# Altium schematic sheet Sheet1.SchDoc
size 431 x 279 mm; SheetNumber: 1; SheetTotal: 1; ENG_APP_DATE: --/--/--; DSN_APP_DATE: --/--/--; CHK_APP_DATE: --/--/--
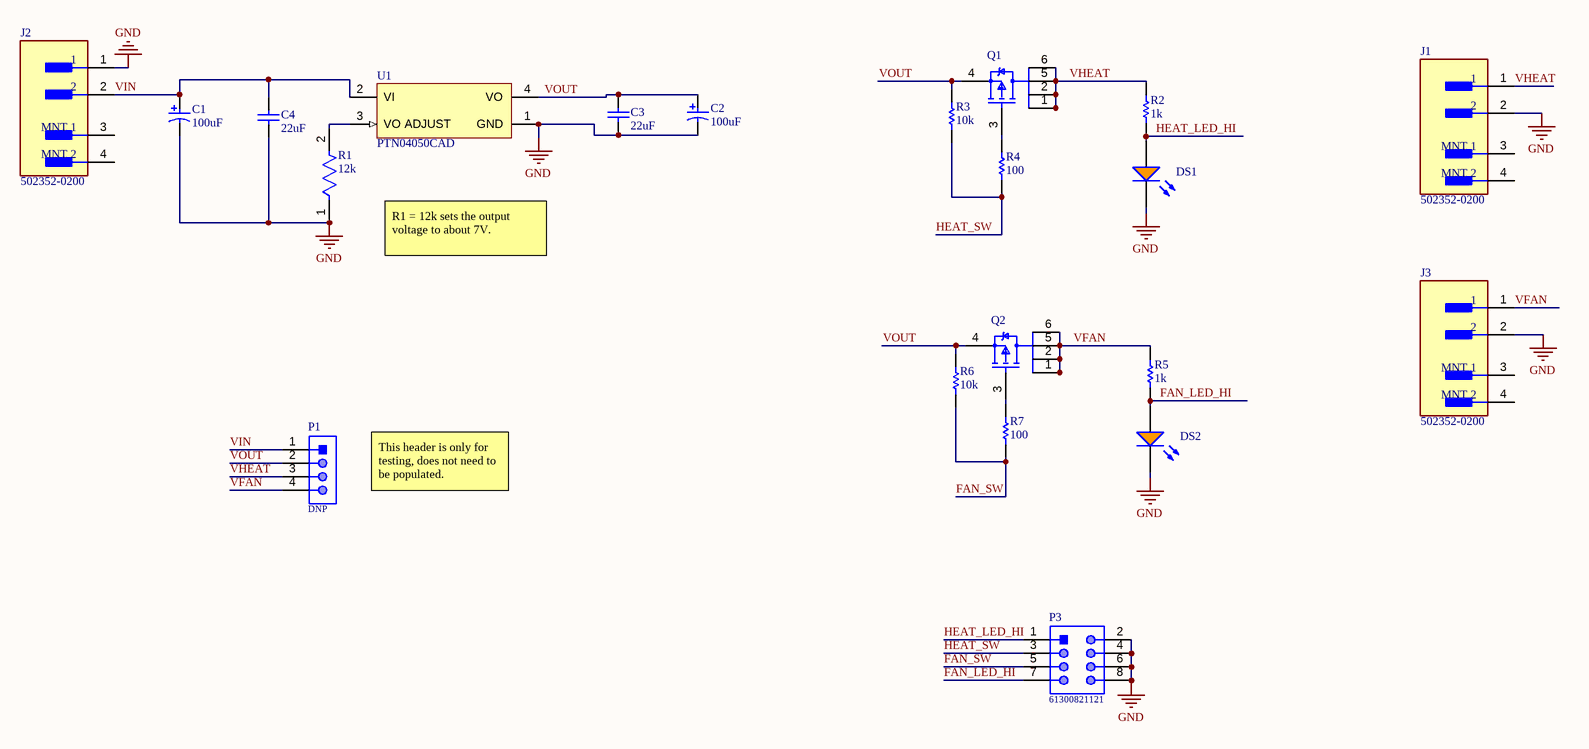
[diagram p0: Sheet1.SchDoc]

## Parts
C1  100uF  [PNSC-FK-V-D8_V]
C2  100uF  [PNSC-FK-V-D8_V]
C3  22uF  [MURA-1210_H_2.7_L]
C4  22uF  [MURA-1210_H_2.7_L]
DS1  HSMD-C170  [AVAG-HSMX-C170_V]  (value not drawn)
DS2  HSMD-C170  [AVAG-HSMX-C170_V]  (value not drawn)
J1  502352-0200  [FP-502352-0200-MFG]
J2  502352-0200  [FP-502352-0200-MFG]
J3  502352-0200  [FP-502352-0200-MFG]
P1  DNP  [61300411121]
P3  61300821121  [61300821121]
Q1  SI3493DDV-T1-GE3  [FP-C-06593-MFG]  (value not drawn)
Q2  SI3493DDV-T1-GE3  [FP-C-06593-MFG]  (value not drawn)
R1  12k  [FP-CRCW0805-e3-IPC_A]
R2  1k  [RESC2013X55X40LL15T20]
R3  10k  [RESC2013X60X35NL10T20]
R4  100  [RESC2013X50X30LL20T20]
R5  1k  [RESC2013X55X40LL15T20]
R6  10k  [RESC2013X60X35NL10T20]
R7  100  [RESC2013X50X30LL20T20]
U1  PTN04050CAD  [EUU0004A]

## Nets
GND: C1.2 C2.2 C3.1 C4.2 DS1.2(K) DS2.2(K) J1.2 J2.1 J3.2 P3.2 P3.4 P3.6 P3.8 R1.1 U1.1(GND)
FAN_LED_HI: DS2.1(A) P3.7 R5.1
FAN_SW: P3.5 R6.2 R7.1
HEAT_LED_HI: DS1.1(A) P3.1 R2.1
HEAT_SW: P3.3 R3.2 R4.1
VFAN: J3.1 P1.4 Q2.1(D) Q2.2(D) Q2.5(D) Q2.6(D) R5.2
VHEAT: J1.1 P1.3 Q1.1(D) Q1.2(D) Q1.5(D) Q1.6(D) R2.2
VIN: C1.1 C4.1 J2.2 P1.1 U1.2(VI)
VOUT: C2.1 C3.2 P1.2 Q1.4(S) Q2.4(S) R3.1 R6.1 U1.4(VO)
NetQ1_3: Q1.3(G) R4.2
NetQ2_3: Q2.3(G) R7.2
NetR1_2: R1.2 U1.3(VO_ADJUST)

Not connected (* = marked no-connect by the designer): J1 3(MNT_1) 4(MNT_2); J2 3(MNT_1) 4(MNT_2); J3 3(MNT_1) 4(MNT_2)

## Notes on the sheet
- R1 = 12k sets the output voltage to about 7V.
- This header is only for testing, does not need to be populated.

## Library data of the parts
C1 C2 = CMP-2000-06206-1: Aluminum Electrolytic Capacitor, 100 uF, +/- 20%, 25 V, 2-Pin SMD (Size Code D8), -55 to 105 degC, RoHS, Tape and Reel; Manufacturer: Panasonic; Type: Can; Lifetime@Temperature: 2000Hrs@105°C; Capacitance: 100µF; Rated Voltage: 25V; Ripple Current: 280mA; Impedance: 0.34O
C3 C4 = CMP-2000-06361-1: Chip Monolithic Ceramic Capacitor, 22 uF, +/- 10%, -55 to 85 degC, 2-Pin SMD (1210), RoHS, Tape and Reel; Manufacturer: Murata; Product Training Modules: High-CapMultilayerCeramicCapacitors; Other Names: 490-1882-2; Online Catalog: GRMSeries; Voltage Rating DC: 16V; Temperature Coefficient: X5R; Capacitance: 22µF; Catalog Drawings: GRMSeries_1210_2.5; Featured Product: GA3SafetyRecognizedCapsandHi-CapMLCC
DS1 DS2 = CMP-2000-06421-1: LED Uni-Color Orange, 52 mW, 20 mA, -40 to 85 degC, 2-Pin SMD, RoHS, Tape and Reel; Manufacturer: Avago; Forward Current If Max: 20mA; External Length / Height: 2mm; Luminous Intensity: 8mcd; Lens Shape: Rectangular; Bulb Size: 1.25mmx1.4mm; External Width: 1.25mm; Wavelength Typ: 605nm; Dominant Wavelength: 604nm; PIV Max: 5V; Opto Mounting Orientation: Top; Viewing Angle: 170°; LED Type: Standard; Forward Voltage: 2.2V; SVHC: NoSVHC(19-Dec-2012); No. of Pins: 2; External Depth: 0.8mm; Power Dissipation Pd: 52mW
J1 J3 = CMP-04776-000115-1: CONN HEADER SMD R/A 2POS 2MM; Manufacturer: Molex; Number Of Contacts: 2; Current Rating: 3A; Conn Gender: Male; Conn Orientation: Right Angle; Voltage Rating: 125V
J2 = CMP-04776-000115-1: CONN HEADER SMD R/A 2POS 2MM; Manufacturer: Molex; Number Of Contacts: 2; Current Rating: 3A; Conn Gender: Male; Conn Orientation: Right Angle; Voltage Rating: 125V; System: Connector
P1 = CMP-1502-01064-1: THT Vertical Pin Header WR-PHD, Pitch 2.54 mm, Single Row, 4 pins; Manufacturer: Wurth Elektronik; Withstanding Voltage: 500VAC; Rated Current: 3A; Working Voltage: 250VAC; Pin Number: 4; Gender: Male; Contact Resistance: 20mOhm; Pitch: 2.54mm
P3 = CMP-1502-01078-1: THT Vertical Pin Header WR-PHD, Pitch 2.54 mm, Dual Row, 8 pins; Manufacturer: Wurth Elektronik; Contact Resistance: 20mOhm; Rated Current: 3A; Working Voltage: 250VAC; Pin Number: 8; Withstanding Voltage: 500VAC; Pitch: 2.54mm; Gender: Male
Q1 Q2 = CMP-02550-000156-1: MOSFET P-CHANNEL 20V 8A 6TSOP; Manufacturer: Vishay; Rthja Max: 62.5°C/W; Number Of Channels: 1; Reverse Recovery Time: 21ns; Max Forward Diode Voltage: -1.2V; Threshold Vgs Min: -0.4V; Turn Off Delay Time: 95ns; Input Capacitace At Vds: 1825pF @ -10V; Typ Forward Diode Voltage: -0.8V; Threshold Vgs Max: -1V; Continuous Drain Current: -7.5A; Gate Charge At Vgs: 34.8nC @ -8V; Depletion Mode: False; Drain To Source Breakdown Voltage: -20V; Pulse Drain Current: -32A; Reverse Recovery Charge: 34.8nC; Transconductance: 30S; Max Junction Temp: +150°C; Standoff Height: 0.01mm; Drain To Source Resistance: 0.02Ω; Power Dissipation: 2W; Turn On Delay Time: 25ns; Gate To Source Voltage: 8V
R1 = CMP-2001-04934-2: RES Thick Film, 12kΩ, 1%, 0.125W, 100ppm/°C, 0805; Power Rating: 125mW; Voltage Rating (DC): 150V; Resistance: 12kR
R2 R5 = CMP-2001-04738-1: TNPW08051K00BEEN; Manufacturer: Vishay Dale
R3 R6 = CMP-1659-00013-4: Chip Resistor, 10 KOhm, +/- 1%, 0.125 W, -55 to 155 degC, 0805 (2012 Metric), RoHS, Tape and Reel; Manufacturer: Yageo; Voltage Rating: 150 V
R4 R7 = CMP-2001-04901-1: Manufacturer: Vishay Dale; Part Number: CRCW0805100RFKEA
U1 = CMP-0387-00658-2: 12 W, 3.3 / 5 V Input, Wide Adjust Output Boost Converter, -40 to 85 degC, 4-pin Module (EUU4), Pb-Free (RoHS); Manufacturer: Texas Instruments; Vin(Min)(V): 2.95; VO Adjustable: TRUE; Vin(Max)(V): 5.5; Iout(Max)(A): 2.4; Regulated Outputs(#): 1; Vout(Min)(V): 5; Vout(Max)(V): 15; SubFamily: Non-Isolated POL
